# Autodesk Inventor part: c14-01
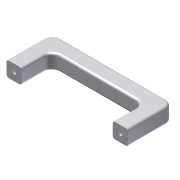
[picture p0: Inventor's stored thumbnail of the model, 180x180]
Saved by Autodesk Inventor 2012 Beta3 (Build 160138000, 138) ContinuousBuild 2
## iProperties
Created: 2011-01
Part Number: c14-01
Material: Default
Document SubType Name: Modeling
Designer: Beta-8540w
Density: 1 g/cm^3
Author: Beta-8540w
Translation Standard: STEP AP214IS
FileName: C:\Inventor 2012 Essentials\Parts\Chapter 14\c14-01.stp
PreProcessor: Autodesk Inventor 2012
PostProcessor: Build: 138a, Release: 2012 Beta3 - Date: Fri 01/21/2011
Sent Units: millimeter
Uncertainty: 0.01
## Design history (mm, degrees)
node "c14-01"
body "Solid1"
node "Base1"
